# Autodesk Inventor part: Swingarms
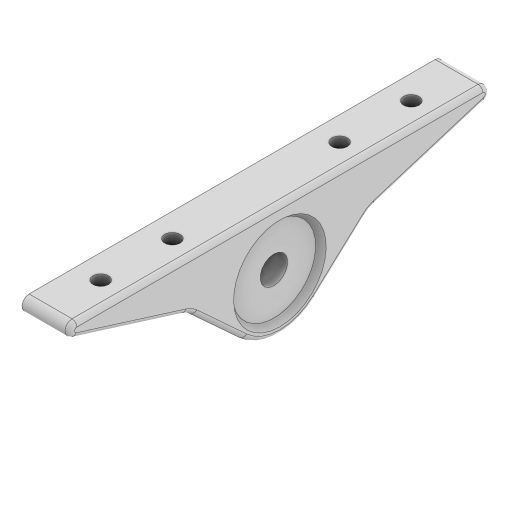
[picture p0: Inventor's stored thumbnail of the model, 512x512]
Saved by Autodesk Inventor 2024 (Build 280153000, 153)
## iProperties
Created: 2024-06
Part Number: Swingarms
Material: Generic
Document SubType Name: Modeling
Designer: simon
Density: 1 g/cm^3
Appearance: Default
Author: simon
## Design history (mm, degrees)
sketch "Sketch1"
  geometry: L1 (-16.566, -15.226)-(2.602, -36.081); L2 (4.786, -39.871)-(19.136, -85.893); L3 (25, -85)-(25, 0); L4 (22.5, 0)-(25, 0); L5 (-16.566, 15.226)-(2.602, 36.081); L6 (4.786, 39.871)-(19.136, 85.893); L7 (25, 85)-(25, 0); L8 (-32.077, 0)-(34.96, 0) reference; C1 r 5 at (0, 0); A1 r 22.5 centre (0, 0) between (-16.566, -15.226) and (22.5, 0); A2 r 3 centre (22, -85) between (19.136, -85.893) and (25, -85); A3 r 10 centre (-4.761, -42.848) between (4.786, -39.871) and (2.602, -36.081); A4 r 3 centre (22, 85) between (25, 85) and (19.136, 85.893); A5 r 10 centre (-4.761, 42.848) between (2.602, 36.081) and (4.786, 39.871); 2 further points
  constraints: 14 end point, 10 point on circle, 7 symmetric about line, 6 centre point, 5 tangent, 2 coincident, 1 collinear, 1 horizontal, 1 vertical, 2 other
  dimensions: "d0" = 10 diameter of C1; "d1" = 45 diameter of A1; "d2" = 3 radius of A2; "d3" = 85 distance of L3.end L3.start; "d4" = 10 radius of A3; "d5" = 25 distance from line of L3 point (0, 0)
extrude "Extrusion1" new body sketch "Sketch1" distance "d6" = 20; taper "d7" = 0 deg
sketch "Sketch2"
  geometry: L1 (0, 0)-(20, 0) reference; L2 (10, 0)-(10, 170.893); L3 (0, 170.893)-(20, 170.893) reference; L4 (0, 85)-(20, 85); L5 (20, 90)-(20, 80) reference; C1 r 3.25 at (10, 20); C2 r 3.25 at (10, 50); C3 r 3.25 at (10, 150); C4 r 3.25 at (10, 120)
  constraints: 4 centre point, 4 end point, 3 midpoint, 2 point on line, 2 symmetric about line, 1 equal radius, 2 other
  dimensions: "d8" = 20 distance from line of L1 C1.centre; "d9" = 30 distance of C1.centre C2.centre; "d10" = 6.5 diameter of C1
extrude "Extrusion2" cut sketch "Sketch2" extent not by distance; stored distance "d11" = 0; taper "d12" = 0 deg
workplane "Work Plane1"
sketch "Sketch3"
  geometry: C1 r 3.25 at (10, 20) reference; C2 r 3.25 at (10, 150) reference; C3 r 6.5 at (10, 20); C4 r 6.5 at (10, 150); C5 r 3.25 at (10, 50) reference; C6 r 6.5 at (10, 50); C7 r 3.25 at (10, 120) reference; C8 r 6.5 at (10, 120); 3 further points
  constraints: 4 centre point, 4 coincident, 3 equal radius
  dimensions: "d14" = 13 diameter of C3
extrude "Extrusion3" cut sketch "Sketch3" distance "d15" = 90; taper "d16" = 0 deg
thicken "Thicken1" dims "d17" = 0.75, "d18" = 1
sketch "Sketch4"
  geometry: L1 (17.5, -0.042)-(17.5, 17.458); L2 (17.5, 17.458)-(27.5, 24.958); L3 (27.5, 24.958)-(27.5, -0.042); L4 (27.5, -0.042)-(17.5, -0.042); L5 (20, 19.136)-(20, 4.786) reference; 2 further points
  constraints: 8 end point, 2 vertical, 1 midpoint, 1 perpendicular
  dimensions: "d20" = 35 diameter of L1.end L4; "d21" = 50 diameter of L2.end L4; "d23" = 10 distance of L3.end L1.start; "d24" = 2.5 distance between parallel lines of L5 L1
revolve "Revolution1" sketch "Sketch4" stored, may be unused: angle "d25" = 90 deg
workplane "Work Plane2"
sketch "Sketch7"
  geometry: L1 (7.588, 44)-(4.072, 49.97); L2 (4.072, 49.97)-(7.484, 56); L3 (7.484, 56)-(14.412, 56.06); L4 (14.412, 56.06)-(17.928, 50.09); L5 (17.928, 50.09)-(14.516, 44.06); L6 (14.516, 44.06)-(7.588, 44); L7 (7.588, 44)-(0, 44); L8 (0, 48.919)-(0, 45.129) reference; L9 (7.484, 56)-(0, 56); L10 (0, 44)-(0, 56); L11 (0, 48.919)-(0, 69.774) reference; L12 (0, 85)-(20, 85); L13 (20, 170)-(20, 0) reference; L14 (7.588, 126)-(0, 126); L15 (7.588, 126)-(4.072, 120.03); L16 (0, 126)-(0, 114); L17 (4.072, 120.03)-(7.484, 114); L18 (7.484, 114)-(0, 114); L19 (14.516, 125.94)-(7.588, 126); L20 (7.484, 114)-(14.412, 113.94); L21 (17.928, 119.91)-(14.516, 125.94); L22 (14.412, 113.94)-(17.928, 119.91); L23 (0, 121.081)-(0, 124.871); A1 r 3.25 centre (10, 50) between (13.065, 48.919) and (6.935, 48.919) reference; A2 r 3.25 centre (10, 120) between (6.935, 121.081) and (13.065, 121.081); 4 further points
  constraints: 40 end point, 14 symmetric about line, 2 horizontal, 2 point on circle, 2 point on line, 1 centre point, 1 collinear, 1 midpoint, 14 other
  dimensions: "d34" = 12 distance between parallel lines of L9 L7; "d35" = 6 distance from line of L7 A1.centre; "d36" = 1 horizontal distance of point (11, 50.03) A1.centre
extrude "Extrusion6" cut sketch "Sketch7" distance "d37" = 6.5; taper "d38" = 0 deg
fillet "Fillet1" dims "d42" = 2
body "Solid1"
other parameters: "d33" = -8
